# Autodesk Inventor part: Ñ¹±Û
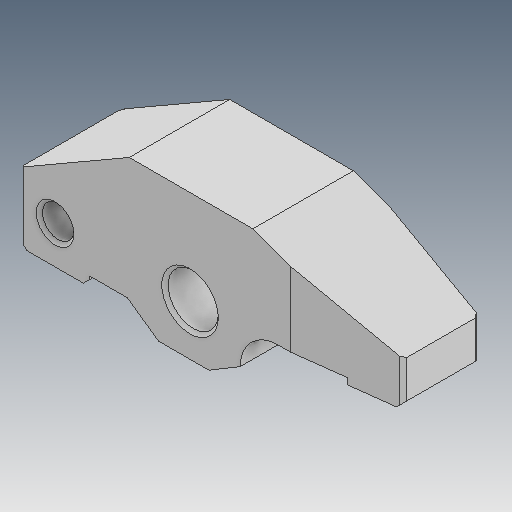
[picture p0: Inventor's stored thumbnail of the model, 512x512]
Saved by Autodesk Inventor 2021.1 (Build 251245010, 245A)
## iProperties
Created: 2013-04
Part Number: Ñ¹±Û
Material: Ogólny
Document SubType Name: Modeling
Designer: user
Density: 1 g/cm^3
Appearance: Domyślna
Author: user
Revision Number: ÈÎºÎ
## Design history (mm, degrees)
feature "µ¹½Ç3"
node "Bryła1"
